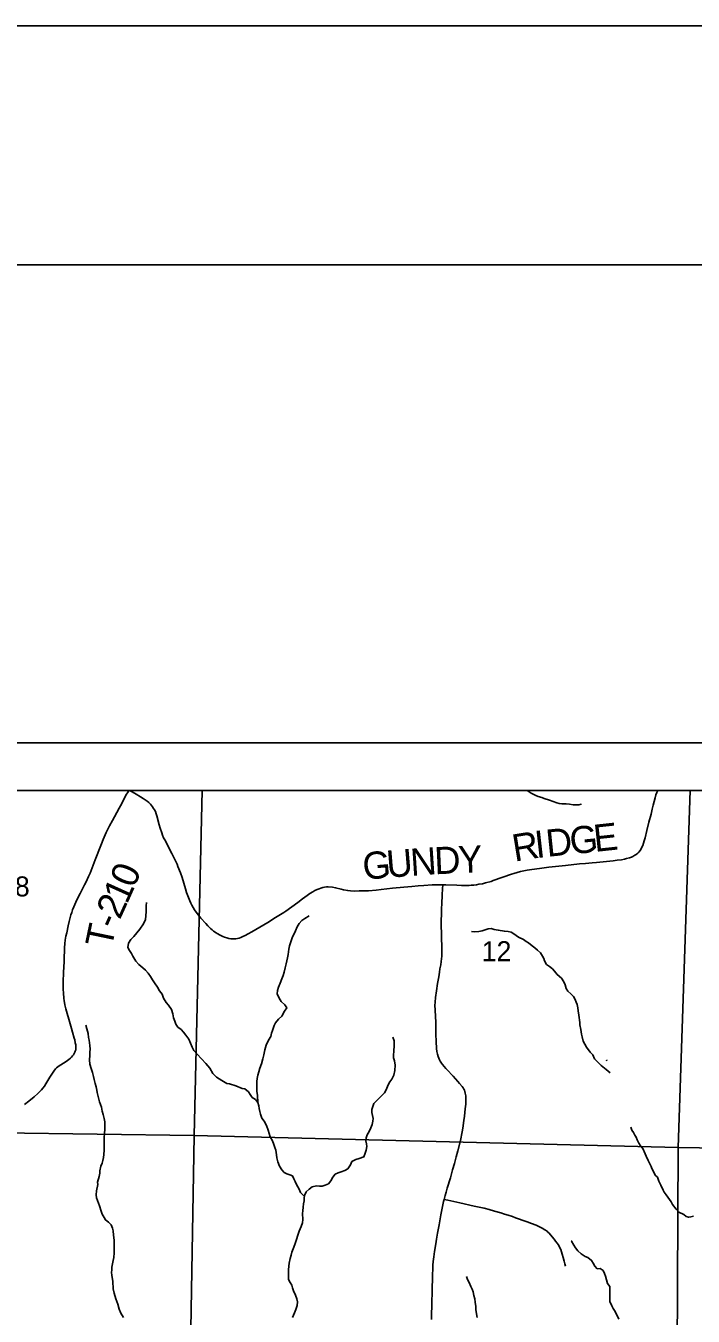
# Model space of a CAD drawing. Extents: x 0 to 34, y 0 to 22.
# Drawn here: x 21.94 to 23.337, y 19.3 to 22 of the extents above; entities that cross this region are included whole.
import ezdxf

# ---------------------------------------------------------------- set-up
doc = ezdxf.new("R2010")
doc.units = 0
for name, color, linetype in [('GM_X_Corporation', 7, 'Continuous'), ('GM_X_County_Road', 7, 'Continuous'), ('GM_X_County_Road_Text', 7, 'Continuous'), ('GM_X_Minor_River', 7, 'Continuous'), ('GM_X_Section_Text', 7, 'Continuous'), ('GM_X_Township_Road', 7, 'Continuous'), ('GM_X_Township_Road_Text', 7, 'Continuous'), ('SH_Border', 7, 'Continuous'), ('SH_Cut_Line', 7, 'Continuous'), ('SH_Data', 7, 'Continuous')]:
    doc.layers.add(name, color=color, linetype=linetype)

msp = doc.modelspace()

# ---------------------------------------------------------------- linework, layer by layer
at = {"layer": 'GM_X_Corporation'}
for points in [[(25.4, 19.0068), (25.4, 20.4), (21.2921, 20.4), (21.2757, 19.6748), (21.2742, 19.6071), (21.273, 19.5535), (21.2652, 19.1913), (21.5297, 19.1865), (21.7744, 19.1817), (21.8956, 19.1793), (22.6423, 19.1645), (23.3329, 19.1508), (23.5499, 19.1465), (23.786, 19.1434), (24.169, 19.1418), (24.3186, 19.1409), (24.3186, 19.0261), (24.5766, 19.0222)], [(22.3096, 20.4), (21.2934, 20.4), (21.2769, 19.6922), (22.2928, 19.6778)], [(23.33, 20.4), (22.3096, 20.4), (22.2928, 19.6778), (23.3052, 19.6529)], [(24.343, 20.4), (23.33, 20.4), (23.3052, 19.6529), (24.3281, 19.637)], [(22.2928, 19.6778), (22.2749, 18.6656), (21.2582, 18.6819), (21.2769, 19.6922)], [(22.2928, 19.6778), (23.3052, 19.6529), (23.3004, 18.648), (22.2749, 18.6656)], [(23.3052, 19.6529), (24.3281, 19.637), (24.3248, 19.5084), (24.3084, 18.6368), (23.3004, 18.648)]]:
    msp.add_lwpolyline(points, close=True, dxfattribs=at)
at = {"layer": 'GM_X_County_Road'}
msp.add_lwpolyline([(22.1575, 20.4), (22.1625, 20.3971), (22.171, 20.3923), (22.18, 20.3869), (22.1859, 20.3832), (22.1903, 20.3802), (22.1941, 20.3774), (22.1975, 20.3747), (22.2009, 20.3716), (22.2036, 20.3686), (22.2055, 20.366), (22.2077, 20.3626), (22.2095, 20.3595), (22.2114, 20.3557), (22.213, 20.3509), (22.2143, 20.347), (22.2193, 20.3281), (22.2213, 20.3211), (22.2246, 20.3113), (22.2264, 20.3064), (22.2287, 20.301), (22.2309, 20.2964), (22.2457, 20.2684), (22.2489, 20.2625), (22.2531, 20.2542), (22.2567, 20.2458), (22.2587, 20.2408), (22.2641, 20.2276), (22.2671, 20.2181), (22.2743, 20.194), (22.2768, 20.1862), (22.2791, 20.1799), (22.2836, 20.1691), (22.2855, 20.1644), (22.2878, 20.1597), (22.2905, 20.1548), (22.2932, 20.1503), (22.2964, 20.1457), (22.3035, 20.1361), (22.3062, 20.1328), (22.3167, 20.1214), (22.3213, 20.1165), (22.3264, 20.1114), (22.33, 20.1082), (22.3332, 20.1057), (22.3384, 20.102), (22.341, 20.1005), (22.3469, 20.0972), (22.3522, 20.0946), (22.3563, 20.0929), (22.361, 20.0915), (22.3649, 20.0903), (22.369, 20.0897), (22.3725, 20.0895), (22.3761, 20.0893), (22.3799, 20.0897), (22.3829, 20.0902), (22.387, 20.0912), (22.3899, 20.0922), (22.3946, 20.0942), (22.3996, 20.0963), (22.4054, 20.0997), (22.413, 20.1039), (22.4464, 20.1241), (22.4626, 20.1339), (22.4803, 20.145), (22.484, 20.1475), (22.5092, 20.1658), (22.5191, 20.1731), (22.5287, 20.1802), (22.5349, 20.1842), (22.5408, 20.1879), (22.5452, 20.1904), (22.5498, 20.1927), (22.5541, 20.1944), (22.5574, 20.1956), (22.5617, 20.1969), (22.565, 20.1975), (22.5695, 20.1982), (22.5731, 20.1983), (22.5819, 20.1978), (22.5884, 20.1965), (22.6003, 20.1932), (22.6051, 20.1921), (22.614, 20.1906), (22.6194, 20.1901), (22.6282, 20.1896), (22.6376, 20.1897), (22.6442, 20.1898), (22.6572, 20.1903), (22.6734, 20.1917), (22.6836, 20.1929), (22.7076, 20.1953), (22.7311, 20.1976), (22.748, 20.1993), (22.7615, 20.2006), (22.7732, 20.2015), (22.7905, 20.2024), (22.7983, 20.2026), (22.8127, 20.2027), (22.8191, 20.2027), (22.842, 20.2017), (22.8519, 20.2013), (22.8611, 20.2013), (22.8676, 20.2015), (22.8723, 20.2018), (22.8779, 20.2022), (22.8832, 20.2029), (22.8883, 20.2038), (22.8957, 20.205), (22.902, 20.2065), (22.9137, 20.2098), (22.9183, 20.2114), (22.9565, 20.2249), (22.9616, 20.2266), (22.9686, 20.2287), (22.9755, 20.2303), (22.9894, 20.2331), (22.9944, 20.2339), (23.0203, 20.2374), (23.0347, 20.2393), (23.0698, 20.2432), (23.0991, 20.2462), (23.1115, 20.2474), (23.1256, 20.2488), (23.1342, 20.2496), (23.1693, 20.253), (23.1779, 20.2539), (23.1865, 20.2552), (23.1927, 20.2563), (23.1973, 20.2575), (23.2032, 20.2592), (23.2073, 20.2607), (23.2105, 20.2621), (23.2145, 20.2645), (23.2173, 20.2663), (23.2205, 20.2688), (23.2229, 20.2712), (23.2254, 20.2743), (23.2277, 20.2781), (23.2295, 20.2814), (23.2312, 20.285), (23.233, 20.2895), (23.2344, 20.2943), (23.2362, 20.3008), (23.2398, 20.3165), (23.2441, 20.3334), (23.2484, 20.3507), (23.2509, 20.3612), (23.2527, 20.3693), (23.2568, 20.3847), (23.2588, 20.3909), (23.2607, 20.3957), (23.2621, 20.3987), (23.2627, 20.4)], dxfattribs=at)
at = {"layer": 'GM_X_Minor_River'}
for points in [[(22.9894, 20.4), (22.9912, 20.3987), (22.998, 20.3947), (23.0072, 20.3898), (23.0122, 20.3876), (23.0201, 20.3851), (23.0251, 20.3833), (23.0361, 20.3796), (23.0434, 20.3767), (23.0513, 20.3742), (23.0563, 20.3731), (23.0624, 20.372), (23.0707, 20.3718), (23.0779, 20.3711), (23.0855, 20.3701), (23.0972, 20.3703), (23.1021, 20.3711), (23.1016, 20.3715)], [(22.5233, 19.5503), (22.515, 19.5591), (22.5119, 19.5655), (22.5064, 19.5753), (22.5037, 19.5817), (22.501, 19.5874), (22.4982, 19.5934), (22.4925, 19.5956), (22.4864, 19.5978), (22.4807, 19.6008), (22.4757, 19.6064), (22.4714, 19.614), (22.4679, 19.6227), (22.4655, 19.6314), (22.4646, 19.6375), (22.4634, 19.6473), (22.4614, 19.653), (22.4594, 19.6595), (22.4563, 19.6666), (22.4516, 19.6753), (22.4492, 19.6825), (22.4472, 19.689), (22.4437, 19.6988), (22.439, 19.7082), (22.4344, 19.7146), (22.4316, 19.7226), (22.4296, 19.7286), (22.4284, 19.7347), (22.4279, 19.7404), (22.4259, 19.7469), (22.4209, 19.7533), (22.414, 19.7577), (22.4094, 19.7637), (22.4059, 19.7694), (22.3986, 19.7754), (22.3929, 19.7764), (22.38, 19.7823), (22.3667, 19.7859), (22.361, 19.787), (22.3503, 19.7929), (22.3396, 19.8003), (22.3319, 19.8075), (22.3253, 19.8192), (22.3168, 19.8289), (22.3076, 19.8383), (22.2987, 19.8484), (22.2922, 19.8559), (22.2883, 19.8627), (22.2813, 19.8794), (22.2754, 19.888), (22.2704, 19.8941), (22.2654, 19.8997), (22.2585, 19.9049), (22.2543, 19.9109), (22.2519, 19.9174), (22.2496, 19.9242), (22.2479, 19.9329), (22.2448, 19.9416), (22.2389, 19.9507), (22.2339, 19.9567), (22.2285, 19.9657), (22.2254, 19.974), (22.2203, 19.9808), (22.2157, 19.9887), (22.2095, 19.9974), (22.2056, 20.0038), (22.2013, 20.011), (22.1963, 20.0178), (22.1909, 20.0241), (22.1852, 20.0286), (22.1771, 20.0361), (22.1702, 20.0432), (22.164, 20.053), (22.1613, 20.0587), (22.157, 20.0651), (22.1535, 20.0715), (22.1549, 20.0807), (22.1597, 20.088), (22.166, 20.0945), (22.1727, 20.1019), (22.1791, 20.11), (22.1865, 20.1207), (22.1905, 20.1299), (22.1912, 20.1379), (22.1918, 20.1471), (22.1921, 20.1528), (22.1924, 20.1589), (22.1926, 20.1657)], [(22.426, 19.7468), (22.4253, 19.7617), (22.4237, 19.7708), (22.4234, 19.7914), (22.4241, 19.7975), (22.4259, 19.804), (22.428, 19.8112), (22.4302, 19.8192), (22.4335, 19.828), (22.436, 19.8384), (22.4385, 19.8468), (22.4402, 19.8571), (22.4435, 19.8674), (22.4479, 19.8777), (22.4527, 19.8854), (22.4545, 19.8923), (22.4567, 19.898), (22.4599, 19.908), (22.4629, 19.9137), (22.4688, 19.9215), (22.4763, 19.928), (22.4814, 19.938), (22.4863, 19.9453), (22.4824, 19.9517), (22.4747, 19.9585), (22.4704, 19.9652), (22.4665, 19.9747), (22.4668, 19.9812), (22.469, 19.9884), (22.4723, 19.9969), (22.4763, 20.0061), (22.4788, 20.0126), (22.4806, 20.0198), (22.4828, 20.029), (22.4849, 20.0374), (22.4863, 20.0435), (22.4878, 20.05), (22.4892, 20.0569), (22.4899, 20.0626), (22.4909, 20.0683), (22.4919, 20.0752), (22.4959, 20.0878), (22.4985, 20.0936), (22.5018, 20.1001), (22.5044, 20.1062), (22.508, 20.115), (22.5125, 20.1219), (22.5181, 20.1277), (22.5241, 20.132), (22.5334, 20.1379)], [(22.8728, 20.1046), (22.8788, 20.1043), (22.8879, 20.1049), (22.8951, 20.1061), (22.9011, 20.1085), (22.9075, 20.1105), (22.9143, 20.111), (22.9204, 20.1092), (22.9288, 20.1078), (22.9417, 20.1053), (22.9496, 20.1047), (22.9557, 20.1032), (22.9615, 20.0999), (22.9714, 20.0932), (22.9817, 20.088), (22.987, 20.0843), (22.9924, 20.0813), (22.9997, 20.0746), (23.005, 20.0705), (23.0112, 20.0656), (23.0173, 20.0604), (23.0212, 20.0532), (23.0239, 20.0483), (23.0259, 20.0434), (23.0298, 20.0359), (23.0359, 20.0314), (23.042, 20.0265), (23.0463, 20.0216), (23.0524, 20.0153), (23.0609, 20.0074), (23.0663, 19.9999), (23.0686, 19.9931), (23.071, 19.9855), (23.0745, 19.9802), (23.0807, 19.9746), (23.0864, 19.9686), (23.0895, 19.9626), (23.0919, 19.9573), (23.0942, 19.9523), (23.0951, 19.9455), (23.0959, 19.9391), (23.0976, 19.9299), (23.0993, 19.9147), (23.0998, 19.9094), (23.1014, 19.8996), (23.1031, 19.8904), (23.1043, 19.8844), (23.1067, 19.8753), (23.1137, 19.8628), (23.1214, 19.8527), (23.1264, 19.8467), (23.1303, 19.8387), (23.1392, 19.8293), (23.1442, 19.8245), (23.1549, 19.8163), (23.1628, 19.8089)], [(22.0986, 19.7377), (22.0946, 19.7486), (22.093, 19.7539), (22.0914, 19.76), (22.0898, 19.768), (22.0886, 19.7729), (22.0873, 19.7797), (22.0853, 19.7869), (22.0833, 19.7953), (22.0821, 19.8017), (22.0797, 19.8097), (22.0769, 19.8184), (22.0745, 19.8271), (22.0736, 19.8362), (22.0743, 19.8454), (22.0745, 19.8526), (22.0748, 19.8587), (22.0743, 19.8663), (22.0727, 19.8777), (22.0718, 19.883), (22.0709, 19.8914), (22.0682, 19.9012), (22.0661, 19.9092)], [(22.4984, 19.2974), (22.5024, 19.3069), (22.505, 19.3138), (22.5079, 19.3226), (22.5089, 19.3299), (22.5073, 19.3363), (22.5049, 19.3439), (22.5006, 19.353), (22.4986, 19.359), (22.497, 19.3647), (22.4935, 19.3707), (22.49, 19.3771), (22.4898, 19.3897), (22.4901, 19.3973), (22.4907, 19.4049), (22.4914, 19.4107), (22.4932, 19.4206), (22.4953, 19.4275), (22.4971, 19.434), (22.4997, 19.4412), (22.503, 19.45), (22.507, 19.4608), (22.5095, 19.4696), (22.5124, 19.4776), (22.5164, 19.4879), (22.519, 19.4956), (22.52, 19.5021), (22.5194, 19.515), (22.5197, 19.5207), (22.5207, 19.5283), (22.5214, 19.5352), (22.5225, 19.5413), (22.5227, 19.5482), (22.5242, 19.5539), (22.5271, 19.5604), (22.5331, 19.5658), (22.5394, 19.5705), (22.5485, 19.5725), (22.5549, 19.5719), (22.5606, 19.5723), (22.5663, 19.5743), (22.5734, 19.5767), (22.5783, 19.5829), (22.5827, 19.5909), (22.5879, 19.5975), (22.5935, 19.5999), (22.5999, 19.6019), (22.6079, 19.6046), (22.6142, 19.6085), (22.6198, 19.617), (22.6227, 19.6235), (22.631, 19.6282), (22.6378, 19.6298), (22.6476, 19.6334), (22.6505, 19.6411), (22.6527, 19.6476), (22.6537, 19.6548), (22.6529, 19.6605), (22.652, 19.667), (22.6523, 19.6735), (22.6545, 19.6792), (22.6585, 19.6865), (22.6622, 19.6938), (22.6651, 19.7011), (22.6662, 19.7079), (22.6668, 19.7136), (22.666, 19.7201), (22.664, 19.7265), (22.6643, 19.7322), (22.6661, 19.7391), (22.6687, 19.7453), (22.6772, 19.7541), (22.6855, 19.7615), (22.691, 19.7673), (22.6947, 19.775), (22.6976, 19.7826), (22.7021, 19.7903), (22.7062, 19.7961), (22.7106, 19.8045), (22.7127, 19.8144), (22.7133, 19.8255), (22.7116, 19.8346), (22.7097, 19.8403), (22.7096, 19.8471), (22.7106, 19.854), (22.7112, 19.8669), (22.7107, 19.8761), (22.7083, 19.884)], [(23.1561, 19.8345), (23.155, 19.8364)], [(22.1447, 19.2976), (22.1393, 19.3063), (22.1358, 19.3146), (22.133, 19.3252), (22.1286, 19.3366), (22.1251, 19.3483), (22.1234, 19.3574), (22.1221, 19.3723), (22.12, 19.3856), (22.1199, 19.3913), (22.1202, 19.397), (22.1205, 19.4023), (22.1229, 19.4164), (22.1244, 19.4225), (22.125, 19.4328), (22.1252, 19.4397), (22.125, 19.4591), (22.1241, 19.4693), (22.1232, 19.4785), (22.1219, 19.4845), (22.1188, 19.491), (22.1131, 19.4966), (22.1073, 19.5014), (22.1042, 19.5063), (22.1003, 19.5135), (22.098, 19.5196), (22.0944, 19.5309), (22.0901, 19.5419), (22.0881, 19.548), (22.0876, 19.5537), (22.0882, 19.5624), (22.0907, 19.5758), (22.0906, 19.5807), (22.0935, 19.5922), (22.0949, 19.5991), (22.0952, 19.6044), (22.0973, 19.6136), (22.0999, 19.6205), (22.1013, 19.6258), (22.1027, 19.6323), (22.1038, 19.638), (22.1044, 19.6475), (22.1042, 19.6624), (22.1044, 19.6734), (22.1047, 19.6829), (22.1053, 19.6909), (22.1056, 19.6986), (22.1054, 19.7069), (22.1042, 19.7134), (22.1022, 19.7221), (22.1002, 19.7289), (22.0986, 19.7377)], [(23.3373, 19.5093), (23.332, 19.5082), (23.3271, 19.507), (23.3217, 19.5086), (23.3168, 19.5127), (23.3069, 19.5176), (23.3008, 19.5241), (23.2932, 19.5339), (23.2909, 19.5396), (23.2833, 19.5491), (23.2798, 19.554), (23.276, 19.5593), (23.2737, 19.5639), (23.2691, 19.5741), (23.2649, 19.5825), (23.2618, 19.5908), (23.2573, 19.595), (23.2546, 19.6011), (23.25, 19.6087), (23.2489, 19.6132), (23.2458, 19.6185), (23.2424, 19.6261), (23.2385, 19.6345), (23.2359, 19.6394), (23.2313, 19.6508), (23.2267, 19.6568), (23.2229, 19.6622), (23.2194, 19.669), (23.2175, 19.6743), (23.2148, 19.6789), (23.2118, 19.6842), (23.2083, 19.6895), (23.2064, 19.6952)], [(23.1623, 19.3623), (23.1573, 19.3684), (23.1556, 19.3763), (23.1529, 19.3835), (23.1509, 19.3896), (23.1482, 19.3956), (23.1421, 19.3997), (23.136, 19.3989), (23.131, 19.4049), (23.1271, 19.4109), (23.124, 19.4166), (23.1164, 19.4225), (23.1106, 19.4251), (23.1026, 19.4307), (23.0953, 19.4367), (23.0903, 19.4427), (23.0868, 19.4487), (23.0821, 19.457), (23.0814, 19.4567)], [(22.8846, 19.2976), (22.8833, 19.3048), (22.8821, 19.3139), (22.8816, 19.3204), (22.8803, 19.3295), (22.8795, 19.3363), (22.8778, 19.3431), (22.8766, 19.3507), (22.8742, 19.3564), (22.8711, 19.3621), (22.868, 19.3704), (22.8645, 19.3768), (22.8625, 19.3832)], [(23.1813, 19.2937), (23.1736, 19.3097), (23.1694, 19.3161), (23.1667, 19.3214), (23.1625, 19.3305), (23.1624, 19.3622)]]:
    msp.add_lwpolyline(points, dxfattribs=at)
at = {"layer": 'GM_X_Township_Road'}
for points in [[(21.9379, 19.7432), (21.9466, 19.7496), (21.9581, 19.7593), (21.9656, 19.766), (21.9713, 19.7716), (21.9733, 19.7738), (21.976, 19.777), (21.9793, 19.7814), (21.9822, 19.7859), (21.9909, 19.8001), (21.9987, 19.8126), (22.0027, 19.8175), (22.0046, 19.8194), (22.007, 19.8215), (22.01, 19.8237), (22.0135, 19.826), (22.0246, 19.8331), (22.0275, 19.8352), (22.0304, 19.8372), (22.0336, 19.8398), (22.036, 19.8422), (22.0382, 19.8445), (22.0401, 19.8471), (22.0414, 19.8496), (22.0427, 19.8524), (22.0438, 19.8548), (22.0447, 19.8571), (22.0452, 19.8604), (22.0447, 19.868), (22.0439, 19.8722), (22.0426, 19.8782), (22.0416, 19.8819), (22.0379, 19.8944), (22.0357, 19.902), (22.0329, 19.9115), (22.024, 19.9434), (22.022, 19.9514), (22.0206, 19.9603), (22.0201, 19.9648), (22.0192, 19.9764), (22.0188, 19.9838), (22.0183, 19.9994), (22.0189, 20.0189), (22.0205, 20.0425), (22.0208, 20.0534), (22.021, 20.0621), (22.0214, 20.0711), (22.0218, 20.0798), (22.0225, 20.0865), (22.0243, 20.0954), (22.0258, 20.102), (22.0289, 20.1168), (22.0309, 20.1257), (22.0348, 20.1396), (22.0364, 20.1446), (22.0383, 20.1504), (22.0407, 20.1568), (22.0428, 20.1616), (22.0474, 20.1709), (22.0542, 20.1841), (22.0634, 20.2027), (22.0663, 20.209), (22.0714, 20.22), (22.0749, 20.2273), (22.077, 20.2329), (22.0854, 20.2549), (22.0897, 20.2655), (22.0931, 20.2742), (22.0988, 20.2886), (22.1024, 20.2977), (22.1086, 20.3123), (22.1118, 20.3192), (22.1154, 20.3261), (22.1217, 20.3374), (22.1261, 20.3452), (22.1307, 20.3538), (22.1355, 20.3629), (22.1412, 20.373), (22.147, 20.3846), (22.1511, 20.3921), (22.1531, 20.3952), (22.1561, 20.4)], [(22.789, 19.2928), (22.7892, 19.3051), (22.7897, 19.3213), (22.7906, 19.3587), (22.791, 19.3788), (22.7922, 19.4069), (22.7928, 19.4147), (22.7937, 19.4242), (22.7954, 19.4355), (22.798, 19.4515), (22.7996, 19.4614), (22.8019, 19.4739), (22.8052, 19.491), (22.8088, 19.5121), (22.8145, 19.5403), (22.8154, 19.5443), (22.8174, 19.5522), (22.8196, 19.5598), (22.822, 19.5679), (22.8286, 19.5896), (22.8334, 19.606), (22.8372, 19.6193), (22.8409, 19.6337), (22.8439, 19.6463), (22.8496, 19.6677), (22.8534, 19.6857), (22.8548, 19.6936), (22.8569, 19.7092), (22.858, 19.7183), (22.8598, 19.7341), (22.8607, 19.7439), (22.8609, 19.7488), (22.861, 19.7529), (22.8611, 19.7578), (22.8609, 19.7613), (22.8599, 19.7667), (22.8591, 19.7703), (22.8581, 19.773), (22.8569, 19.7751), (22.8552, 19.7778), (22.8533, 19.7806), (22.8479, 19.7872), (22.8445, 19.7908), (22.8347, 19.8019), (22.8323, 19.8043), (22.823, 19.8138), (22.8191, 19.8181), (22.8122, 19.8266), (22.8101, 19.8294), (22.8076, 19.8334), (22.806, 19.8361), (22.8042, 19.8401), (22.803, 19.8433), (22.8014, 19.8486), (22.8001, 19.8541), (22.7993, 19.86), (22.7989, 19.8745), (22.7985, 19.8898), (22.7979, 19.9162), (22.7973, 19.9265), (22.7965, 19.9413), (22.7964, 19.9499), (22.7969, 19.9574), (22.7977, 19.9667), (22.7995, 19.9808), (22.8019, 19.996), (22.8042, 20.0104), (22.8058, 20.0197), (22.8069, 20.0266), (22.8085, 20.0352), (22.8095, 20.0425), (22.8101, 20.0474), (22.8105, 20.053), (22.8109, 20.0614), (22.8105, 20.0773), (22.8103, 20.0872), (22.8098, 20.0994), (22.8095, 20.1181), (22.8096, 20.1249), (22.8101, 20.1443), (22.8103, 20.1529), (22.8107, 20.1626), (22.8109, 20.1698), (22.8111, 20.1746), (22.8114, 20.181), (22.8116, 20.1852), (22.812, 20.191), (22.8122, 20.1962), (22.8125, 20.2008), (22.8127, 20.2027)], [(22.8154, 19.5443), (22.8235, 19.5426), (22.8482, 19.5373), (22.8782, 19.5305), (22.8991, 19.5257), (22.9096, 19.5231), (22.9209, 19.5199), (22.9339, 19.5161), (22.942, 19.5137), (22.9497, 19.5112), (22.9583, 19.5085), (22.9652, 19.506), (22.9734, 19.5031), (22.9788, 19.501), (22.989, 19.4973), (22.9983, 19.4941), (23.0082, 19.4904), (23.011, 19.4892), (23.014, 19.4878), (23.0209, 19.4841), (23.0262, 19.4809), (23.0308, 19.4777), (23.0328, 19.4757), (23.035, 19.4736), (23.0382, 19.4699), (23.0456, 19.4612), (23.0489, 19.4571), (23.0522, 19.4527), (23.0543, 19.4497), (23.0561, 19.4467), (23.0584, 19.4419), (23.0594, 19.4394), (23.0626, 19.4298), (23.0647, 19.4227), (23.0669, 19.4152), (23.0682, 19.4099), (23.0696, 19.4046)]]:
    msp.add_lwpolyline(points, dxfattribs=at)
at = {"layer": 'SH_Border'}
msp.add_lwpolyline([(1.5, 21.5), (33.5, 21.5), (33.5, 0.5), (1.5, 0.5)], close=True, dxfattribs=at)
at = {"layer": 'SH_Cut_Line'}
msp.add_lwpolyline([(0, 0), (34, 0), (34, 22), (0, 22)], close=True, dxfattribs=at)
at = {"layer": 'SH_Data'}
for points in [[(18.5, 20.5), (25.5, 20.5), (25.5, 13.5), (18.5, 13.5)], [(18.6, 20.4), (25.4, 20.4), (25.4, 13.6), (18.6, 13.6)]]:
    msp.add_lwpolyline(points, close=True, dxfattribs=at)

# ---------------------------------------------------------------- texts
at = {"layer": 'GM_X_County_Road_Text'}
for s, rotation, p in [('E', 6.1537, (23.1311, 20.2713)), ('R', 9.3186, (22.963, 20.2509)), ('I', 6.485, (23.0083, 20.2583)), ('D', 5.9226, (23.0314, 20.261)), ('G', 5.8933, (23.0811, 20.2661)), ('U', 4.6826, (22.697, 20.2172)), ('N', 3.7402, (22.7466, 20.2213)), ('D', 2.5763, (22.7962, 20.2245)), ('Y', 2.3758, (22.8461, 20.2268)), ('G', 4.763, (22.6472, 20.2131))]:
    msp.add_text(s, height=0.0568, rotation=rotation, dxfattribs=at).set_placement(p)
at = {"layer": 'GM_X_Section_Text'}
for s, p in [('18', (21.8862, 20.1783)), ('12', (22.8941, 20.0428))]:
    msp.add_text(s, height=0.04186, rotation=0, dxfattribs=at).set_placement(p)
at = {"layer": 'GM_X_Township_Road_Text'}
for s, rotation, p in [('0', 67.5626, (22.1669, 20.194)), ('1', 65.7938, (22.1518, 20.1603)), ('2', 65.4135, (22.137, 20.1281)), ('T', 78.274, (22.1199, 20.0684)), ('-', 65.9701, (22.1276, 20.1069))]:
    msp.add_text(s, height=0.0568, rotation=rotation, dxfattribs=at).set_placement(p)

doc.saveas('drawing.dxf')
